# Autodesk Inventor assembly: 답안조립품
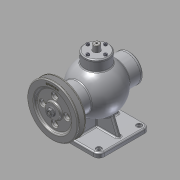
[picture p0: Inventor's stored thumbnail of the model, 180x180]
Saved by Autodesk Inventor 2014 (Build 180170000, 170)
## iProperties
Created: 2015-10
Part Number: 답안조립품
Document SubType Name: Assembly
Designer: youjin15
Author: youjin15
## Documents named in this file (19)
- C:\Users\youjin15\Desktop\451010V1003\답안조립품.iam
- C:\Users\youjin15\Desktop\451010V1003\본체.ipt
- C:\Users\youjin15\Desktop\451010V1003\앞커버.ipt
- C:\Users\youjin15\Desktop\451010V1003\뒤커버.ipt
- C:\Users\youjin15\Desktop\451010V1003\상부커버.ipt
- C:\Users\youjin15\Desktop\451010V1003\볼트 M4 x 16.ipt
- C:\Users\youjin15\Desktop\451010V1003\볼트 M 4 x 12.ipt
- C:\Users\youjin15\Desktop\451010V1003\멈춤링- 15 x 1.ipt
- C:\Users\youjin15\Desktop\451010V1003\멈춤링- 35x1.6.ipt
- KS B 1336 - 35x1.6.ipt
- C:\Users\youjin15\Desktop\451010V1003\베어링- 6202.ipt
- KS B 2023 - 6202 - 15 x 35 x 11 - 7.8.ipt
- C:\Users\youjin15\Desktop\451010V1003\부시.ipt
- C:\Users\youjin15\Desktop\451010V1003\편심축.ipt
- C:\Users\youjin15\Desktop\451010V1003\오일실 15 30 7.ipt
- C:\Users\youjin15\Desktop\451010V1003\키 4 x 4 x 12.ipt
- C:\Users\youjin15\Desktop\451010V1003\V-벨트풀리.ipt
- C:\Users\youjin15\Desktop\451010V1003\너트 M8.ipt
- C:\Users\youjin15\Desktop\451010V1003\슬라이드.ipt
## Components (16 placed, 5 different names)
1. KS B 1336 - 35x1.6:1 — Tangent:2, Mate:21
2. KS B 2023 - 6202 - 15 x 35 x 11 - 7.8:1 — Mate:10, Mate:11
3. KS B 2023 - 6202 - 15 x 35 x 11 - 7.8:2 — Mate:12, Mate:13, Mate:14, Mate:15
4. V-벨트풀리:1 — Mate:27, Flush:1, Mate:28, Mate:29
5. ISO 4762 M4 x 16:2 — Insert:2
6. ISO 4762 M4 x 16:1 — Insert:3
7. ISO 4762 M4 x 16:3
8. ISO 4762 M4 x 16:4
9. ISO 4762 M4 x 16:5
10. ISO 4762 M4 x 16:6
11. ISO 4762 M4 x 16:7
12. ISO 4762 M4 x 16:8
13. KS B 1021 - 에 따름 ISO 1207 - 미터 A  M 4 x 12:1 — Insert:4
14. KS B 1021 - 에 따름 ISO 1207 - 미터 A  M 4 x 12:2
15. KS B 1021 - 에 따름 ISO 1207 - 미터 A  M 4 x 12:3
16. KS B 1021 - 에 따름 ISO 1207 - 미터 A  M 4 x 12:4
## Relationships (15: Mate 10, Insert 3, Tangent 1, Flush 1)
- Insert:2: ISO 4762 M4 x 16:2
- Insert:3: ISO 4762 M4 x 16:1
- Insert:4: KS B 1021 - 에 따름 ISO 1207 - 미터 A  M 4 x 12:1
- Mate:10: KS B 2023 - 6202 - 15 x 35 x 11 - 7.8:1
- Mate:11: KS B 2023 - 6202 - 15 x 35 x 11 - 7.8:1
- Mate:12: KS B 2023 - 6202 - 15 x 35 x 11 - 7.8:2
- Mate:13: KS B 2023 - 6202 - 15 x 35 x 11 - 7.8:2
- Mate:14: KS B 2023 - 6202 - 15 x 35 x 11 - 7.8:2
- Mate:15: KS B 2023 - 6202 - 15 x 35 x 11 - 7.8:2
- Tangent:2: KS B 1336 - 35x1.6:1
- Mate:21: KS B 1336 - 35x1.6:1
- Mate:27: V-벨트풀리:1
- Flush:1: V-벨트풀리:1
- Mate:28: V-벨트풀리:1
- Mate:29: V-벨트풀리:1
